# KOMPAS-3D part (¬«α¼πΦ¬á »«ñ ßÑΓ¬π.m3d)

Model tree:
1. Эскиз:1
2. Операция выдавливания:1
     Расстояние 1 = 8
3. Эскиз:2
4. Операция выдавливания:2
     Расстояние 1 = 40
5. Фаска:2
     Угол = 45; Длина 1 = 7; Длина 2 = 7
6. Скругление:1
     Радиус = 2
7. Скругление:2
     Радиус = 2
8. Скругление:3
     Радиус = 1
9. Скругление:4
     Радиус = 2
10. Скругление:5
     Радиус = 2
